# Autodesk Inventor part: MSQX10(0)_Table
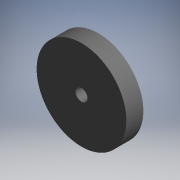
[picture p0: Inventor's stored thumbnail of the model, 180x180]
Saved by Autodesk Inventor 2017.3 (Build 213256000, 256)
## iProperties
Part Number: MSQX10(0)_Table
Material: Generic
Catalog Web Link: www.cadenas.de
Description: MSQ TABLE-Low-Speed Rotary Table Rack & Pinion Style
Vendor: SMC
Document SubType Name: Modeling
Designer: partserver
Manufacturer: SMC
Mass: 11.2196 g
Surface Area: 55.159 cm^2
Volume: 11.2196 cm^3
Density: 1 g/cm^3
Appearance: PSOLRGB-128-128-128
Category: PARTsolutions
Company: SMC
Title: MSQX10_Table
Author: Cadenas PARTsolutions
Comments: Low-Speed Rotary Table Rack & Pinion Style
PSOL_IDENT_0: {$CADENAS_DATA\23d-libs\smc_jp\actuator\rotary_actuator\msqx\parts\msqx_table.prj},177 {VTYP=3D},{NB=
PSOL_IDENT_1: MSQX10(0)_Table},{LINA=MSQX10_Table},{NN=MSQ TABLE},{DATE=09.12.2020 02:49:36},{GEOMDATE=14.08.2019
PSOL_IDENT_2: 05:56:19},{VERSION=},{LINEID=160},{WBVAR=THREAD},{WBNUMERIC=}  {NB=MSQX10(0)_Table},{LINA=MSQX10_Tab
PSOL_IDENT_3: le},{KT=DUMMY},{ORDER=MSQX10},{SIZE=10},{THREAD=0},{AA=55.4},{AB=0},{A=50},{AU=8.6},{AV=20.0},{AW=15
PSOL_IDENT_4: .5},{AX=12},{AY=4},{BA=9.5},{BB=34.5},{BC=27.8},{BD=60},{BE=27},{CA=4.5},{CB=28.5},{D=45h9},{D1=45},
PSOL_IDENT_5: {DD=46h9},{DD1=46},{DE=20H9},{DE1=20},{DF=6},{DG=15H9},{DG1=15},{FA=8.0},{FB=4.0},{FC=3.0},{FD=4.5},
PSOL_IDENT_6: {H=13},{J=6.8},{JA=11.0},{JB=6.5},{JC=M8x1.25},{JC1=8},{JD=12},{JJ=M5x0.8},{JJ1=5},{JK=8},{JU=M8x1},
PSOL_IDENT_7: {JU1=8},{P=M5x0.8},{P1=5.000},{Q=34},{S=92},{SD=9.0},{SE=13},{SF=45},{SU=17.7},{UU=47},{WA=15.0},{WB=
PSOL_IDENT_8: 3H9},{WB1=3},{WC=3.5},{WD=M5x0.8},{WD1=5},{WDP=0.80},{WE=8.0},{WF=32},{XA=27},{XB=3H9},{XB1=3},{XC=3
PSOL_IDENT_9: .5},{YA=19},{YB=3H9},{YB1=3},{YC=3.5},{FU=31.5},{DH=45h8},{DH1=45},{DI=46h8},{DI1=46},{DJ=20H8},{DJ1=
PSOL_IDENT_10: 20},{DK=5},{DL=15H8},{DL1=15},{FE=10.0},{HA=18.5},{UV=52.5},{DA=46h9},{DA1=46},{DB=45h9},{DB1=45},{D
PSOL_IDENT_11: C=20H9},{DC1=20},{DDD=35h9},{DDD1=35},{HHA=15.5},{HB=20/24},{HB1=20},{HB2=24},{HC=5},{HD=59/63},{HD1=
PSOL_IDENT_12: 59},{HD2=63},{HE=9.5},{F1=6.917},{F2=5},{Y1=8},{Y2=12}
NB: MSQX10(0)_Table
NN: MSQ TABLE
NT: Low-Speed Rotary Table Rack & Pinion Style
NBSYN: $ORDER.($THREAD.)_Table
LINA: MSQX10_Table
CATALOG: SMC (JP
SIZE: 10
THREAD: on
AA: 55.4
AB: 0
A: 50
AU: 8.6
AV: 20
AW: 15.5
AX: 12
AY: 4
BA: 9.5
BB: 34.5
BC: 27.8
BD: 60
BE: 27
CA: 4.5
CB: 28.5
D: 45h9
D1: 45
DD: 46h9
DD1: 46
DE: 20H9
DE1: 20
DF: 6
DG: 15H9
DG1: 15
FA: 8
FB: 4
FC: 3
FD: 4.5
H: 13
J: 6.8
JA: 11
JB: 6.5
JC: M8x1.25
JC1: 8
JD: 12
JJ: M5x0.8
JJ1: 5
JK: 8
JU: M8x1
JU1: 8
P: M5x0.8
P1: 5
Q: 34
S: 92
SD: 9
SE: 13
SF: 45
SU: 17.7
UU: 47
WA: 15
WB: 3H9
WB1: 3
WC: 3.5
WD: M5x0.8
WD1: 5
WDP: 0.8
WE: 8
WF: 32
XA: 27
XB: 3H9
XB1: 3
XC: 3.5
YA: 19
YB: 3H9
YB1: 3
YC: 3.5
FU: 31.5
DH: 45h8
DH1: 45
DI: 46h8
DI1: 46
DJ: 20H8
DJ1: 20
DK: 5
DL: 15H8
DL1: 15
FE: 10
HA: 18.5
UV: 52.5
DA: 46h9
DA1: 46
DB: 45h9
DB1: 45
DC: 20H9
DC1: 20
DDD: 35h9
DDD1: 35
HHA: 15.5
HB: 20/24
HB1: 20
HB2: 24
HC: 5
HD: 59/63
HD1: 59
HD2: 63
HE: 9.5
F1: 6.917
F2: 5
Y1: 8
Y2: 12
SUPPLIER: SMC
ARTICLENO: MSQX10(0)_Table
BOMINFO: MSQX10_Table
CREATOR: CADENAS GmbH
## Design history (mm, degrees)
sketch "Sketch_2"
  geometry: L1 (0, -8.5)-(0, -4); L2 (0, -4)-(10, -4); L3 (10, -4)-(10, 0); L4 (10, 0)-(22.5, 0); L5 (22.5, 0)-(22.5, -8.5); L6 (22.5, -8.5)-(0, -8.5); L7 (0, -8.5)-(0, -4)
  constraints: 14 end point
revolve "Revolution1" sketch "Sketch_2" stored, may be unused: angle "d0" = 360 deg
sketch "Sketch_4"
  geometry: L1 (16, 0)-(16, -8); L2 (16, -8)-(13.933, -8); L3 (13.933, -8)-(13.933, -0.433); L4 (13.933, -0.433)-(13.5, 0); L5 (13.5, 0)-(16, 0); L6 (16, 0)-(16, -8)
  constraints: 12 end point
revolve "Revolution2" sketch "Sketch_4" stored, may be unused: angle "d1" = 360 deg
thread "Thread1" dims "d2" = 7.567, "d3" = 0
pattern_circular "Circular Pattern1" dims angle "d5" = 45 deg
sketch "Sketch_1"
  geometry: C1 r 3 at (0, 0); 1 further point
  constraints: 1 centre point
extrude "Extrusion1" cut sketch "Sketch_1" distance "d7" = 13; taper "d8" = 0 deg
sketch "Sketch_19"
  geometry: L1 (7.891, -15.132)-(7.126, -13.284); L2 (4.354, -14.432)-(5.12, -16.28); A1 r 1.5 centre (6.506, -15.706) between (5.12, -16.28) and (7.891, -15.132); A2 r 1.5 centre (5.74, -13.858) between (7.126, -13.284) and (4.354, -14.432)
  constraints: 4 end point, 4 point on circle, 2 centre point
extrude "Extrusion2" cut sketch "Sketch_19" distance "d9" = 3.5; taper "d10" = 0 deg
node "table_set_XY"
node "table_set_YZ"
node "table_set_ZX"
node "table_set_X"
node "table_set_Y"
node "table_set_Z"
node "table_set_Center"
body "Solid1"
other parameters: "d11" = 0
